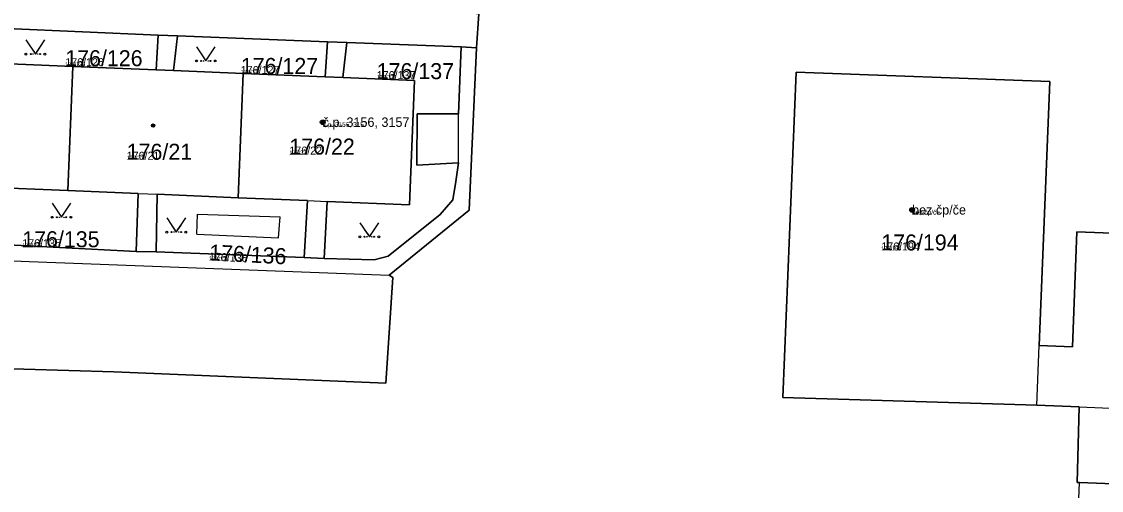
# Model space of a CAD drawing. Extents: x -759873 to -758487, y -975024 to -973516.
# Drawn here: x -759571.4 to -759456.7, y -974909.7 to -974859.9 of the extents above; entities that cross this region are included whole.
import ezdxf

# ---------------------------------------------------------------- set-up
doc = ezdxf.new("R2010")
doc.units = 0
for name, color, linetype in [('KAT_02_hranice parcel', 7, 'Continuous'), ('KAT_03_1000_st čísla parcelní', 7, 'Continuous'), ('KAT_03_1000_čísla parcelní', 7, 'Continuous'), ('KAT_03_1000_čísla popisná', 7, 'Continuous'), ('KAT_03_250_st čísla parcelní', 7, 'Continuous'), ('KAT_03_250_čísla parcelní', 7, 'Continuous'), ('KAT_03_250_čísla popisná', 7, 'Continuous'), ('KAT_03_500_st čísla parcelní', 7, 'Continuous'), ('KAT_03_500_čísla parcelní', 7, 'Continuous'), ('KAT_03_500_čísla popisná', 7, 'Continuous'), ('KAT_04_vnitřní kresba', 7, 'Continuous'), ('KAT_05_1000_značky kultur', 7, 'Continuous'), ('KAT_05_250_značky kultur', 7, 'Continuous'), ('KAT_05_500_značky kultur', 7, 'Continuous'), ('KAT_07_1000_značky budov', 7, 'Continuous'), ('KAT_07_250_značky budov', 7, 'Continuous'), ('KAT_07_500_značky budov', 7, 'Continuous'), ('KAT_14_plocha_budovy', 7, 'Continuous'), ('KAT_14_plocha_pozemek', 7, 'Continuous')]:
    doc.layers.add(name, color=color, linetype=linetype)

msp = doc.modelspace()

# ---------------------------------------------------------------- linework, layer by layer
at = {"layer": 'KAT_02_hranice parcel'}
for p, q in [((-759522.81, -974859.11), (-759523.06, -974862.69)), ((-759572.94, -974860.67), (-759556.86, -974861.35)), ((-759554.8, -974861.42), (-759556.86, -974861.35)), ((-759554.8, -974861.42), (-759538.88, -974862.06)), ((-759536.82, -974862.14), (-759538.88, -974862.06)), ((-759536.82, -974862.14), (-759524.69, -974862.61)), ((-759524.69, -974862.61), (-759523.06, -974862.69)), ((-759566.48, -974877.87), (-759565.93, -974864.69)), ((-759548.38, -974878.62), (-759547.84, -974865.44)), ((-759575.54, -974883.47), (-759559.19, -974884.32)), ((-759559.19, -974884.32), (-759557.09, -974884.36)), ((-759557.09, -974884.36), (-759541.34, -974884.98)), ((-759541.34, -974884.98), (-759539.22, -974885.08))]:
    msp.add_line(p, q, dxfattribs=at)
for points in [[(-759565.93, -974864.69), (-759573.44, -974864.36), (-759572.94, -974860.67)], [(-759556.86, -974861.35), (-759557.08, -974865.04), (-759565.93, -974864.69)], [(-759547.84, -974865.44), (-759555.24, -974865.12), (-759554.8, -974861.42)], [(-759523.06, -974862.69), (-759523.84, -974879.95), (-759532.34, -974886.85), (-759531.93, -974887.1), (-759532.68, -974898.32), (-759561.57, -974897.09), (-759590.3, -974896.25), (-759598.34, -974895.81)], [(-759538.88, -974862.06), (-759539.12, -974865.79), (-759547.84, -974865.44)], [(-759539.22, -974885.08), (-759538.93, -974879.01), (-759530.18, -974879.37), (-759529.64, -974866.18), (-759537.26, -974865.86), (-759536.82, -974862.14)], [(-759539.22, -974885.08), (-759533.93, -974885.2), (-759532.43, -974884.81), (-759526.92, -974880.39), (-759525.57, -974878.84), (-759525.26, -974876.9), (-759524.97, -974874.9), (-759529.38, -974875.18), (-759529.35, -974869.7), (-759524.95, -974869.72), (-759524.69, -974862.61)], [(-759462.14, -974866.29), (-759463.26, -974894.3), (-759459.73, -974894.44), (-759459.28, -974882.23), (-759445.33, -974882.76), (-759445.56, -974888.94), (-759433.43, -974889.26), (-759433.67, -974896.02), (-759433.88, -974901.49), (-759433.89, -974901.85), (-759452.92, -974901.09), (-759453.26, -974909.07), (-759453.61, -974909.06), (-759458.99, -974908.85), (-759459.25, -974908.84), (-759459.03, -974900.84), (-759463.51, -974900.66), (-759490.49, -974899.84), (-759489.09, -974865.28), (-759462.14, -974866.29)], [(-759575.54, -974883.47), (-759575.23, -974877.51), (-759566.48, -974877.87)], [(-759566.48, -974877.87), (-759558.99, -974878.18), (-759559.19, -974884.32)], [(-759557.09, -974884.36), (-759556.96, -974878.26), (-759548.38, -974878.62)], [(-759548.38, -974878.62), (-759541, -974878.92), (-759541.34, -974884.98)]]:
    msp.add_lwpolyline(points, dxfattribs=at)
at = {"layer": 'KAT_03_1000_čísla popisná'}
for centre in [(-759539.39, -974870.6), (-759476.77, -974879.91)]:
    msp.add_circle(centre, 0.25, dxfattribs=at)
at = {"layer": 'KAT_03_250_čísla popisná'}
for centre in [(-759539.39, -974870.6), (-759476.77, -974879.91)]:
    msp.add_circle(centre, 0.0625, dxfattribs=at)
at = {"layer": 'KAT_03_500_čísla popisná'}
for centre in [(-759539.39, -974870.6), (-759476.77, -974879.91)]:
    msp.add_circle(centre, 0.125, dxfattribs=at)
at = {"layer": 'KAT_04_vnitřní kresba'}
for p, q in [((-759557.08, -974865.04), (-759555.24, -974865.12)), ((-759539.12, -974865.79), (-759537.26, -974865.86)), ((-759524.97, -974874.9), (-759524.95, -974869.72)), ((-759558.99, -974878.18), (-759556.96, -974878.26)), ((-759541, -974878.92), (-759538.93, -974879.01)), ((-759552.76, -974882.49), (-759552.69, -974880.35)), ((-759552.69, -974880.35), (-759543.92, -974880.66)), ((-759544.1, -974882.88), (-759543.92, -974880.66)), ((-759552.76, -974882.49), (-759544.1, -974882.88)), ((-759588.86, -974884.55), (-759570.57, -974885.39)), ((-759570.57, -974885.39), (-759564.91, -974885.6)), ((-759564.91, -974885.6), (-759532.34, -974886.85)), ((-759463.51, -974900.66), (-759463.26, -974894.3)), ((-759459.03, -974900.84), (-759452.92, -974901.09)), ((-759460.02, -974931.99), (-759458.99, -974908.85))]:
    msp.add_line(p, q, dxfattribs=at)
at = {"layer": 'KAT_05_1000_značky kultur'}
for points in [[(-759570.91, -974861.87), (-759569.91, -974863.37), (-759568.91, -974861.87)], [(-759552.8, -974862.6), (-759551.8, -974864.1), (-759550.8, -974862.6)], [(-759568.13, -974879.2), (-759567.13, -974880.7), (-759566.13, -974879.2)], [(-759555.94, -974880.77), (-759554.94, -974882.27), (-759553.94, -974880.77)], [(-759535.43, -974881.27), (-759534.43, -974882.77), (-759533.43, -974881.27)]]:
    msp.add_lwpolyline(points, dxfattribs=at)
for centre in [(-759570.91, -974863.37), (-759568.91, -974863.37), (-759552.8, -974864.1), (-759550.8, -974864.1), (-759568.13, -974880.7), (-759566.13, -974880.7), (-759555.94, -974882.27), (-759553.94, -974882.27), (-759535.43, -974882.77), (-759533.43, -974882.77)]:
    msp.add_circle(centre, 0.1, dxfattribs=at)
at = {"layer": 'KAT_05_250_značky kultur'}
for points in [[(-759570.16, -974862.99), (-759569.91, -974863.37), (-759569.66, -974862.99)], [(-759552.05, -974863.72), (-759551.8, -974864.1), (-759551.55, -974863.72)], [(-759567.38, -974880.32), (-759567.13, -974880.7), (-759566.88, -974880.32)], [(-759555.19, -974881.89), (-759554.94, -974882.27), (-759554.69, -974881.89)], [(-759534.68, -974882.39), (-759534.43, -974882.77), (-759534.18, -974882.39)]]:
    msp.add_lwpolyline(points, dxfattribs=at)
for centre in [(-759570.16, -974863.37), (-759569.66, -974863.37), (-759552.05, -974864.1), (-759551.55, -974864.1), (-759567.38, -974880.7), (-759566.88, -974880.7), (-759555.19, -974882.27), (-759554.69, -974882.27), (-759534.68, -974882.77), (-759534.18, -974882.77)]:
    msp.add_circle(centre, 0.025, dxfattribs=at)
at = {"layer": 'KAT_05_500_značky kultur'}
for points in [[(-759570.41, -974862.62), (-759569.91, -974863.37), (-759569.41, -974862.62)], [(-759552.3, -974863.35), (-759551.8, -974864.1), (-759551.3, -974863.35)], [(-759567.63, -974879.95), (-759567.13, -974880.7), (-759566.63, -974879.95)], [(-759555.44, -974881.52), (-759554.94, -974882.27), (-759554.44, -974881.52)], [(-759534.93, -974882.02), (-759534.43, -974882.77), (-759533.93, -974882.02)]]:
    msp.add_lwpolyline(points, dxfattribs=at)
for centre in [(-759570.41, -974863.37), (-759569.41, -974863.37), (-759552.3, -974864.1), (-759551.3, -974864.1), (-759567.63, -974880.7), (-759566.63, -974880.7), (-759555.44, -974882.27), (-759554.44, -974882.27), (-759534.93, -974882.77), (-759533.93, -974882.77)]:
    msp.add_circle(centre, 0.05, dxfattribs=at)
at = {"layer": 'KAT_07_1000_značky budov'}
for centre in [(-759557.41, -974870.96), (-759539.4, -974870.6), (-759476.78, -974879.91)]:
    msp.add_circle(centre, 0.175, dxfattribs=at)
at = {"layer": 'KAT_07_250_značky budov'}
for centre in [(-759557.4, -974870.96), (-759539.39, -974870.6), (-759476.77, -974879.91)]:
    msp.add_circle(centre, 0.0437, dxfattribs=at)
at = {"layer": 'KAT_07_500_značky budov'}
for centre in [(-759557.4, -974870.96), (-759539.39, -974870.6), (-759476.77, -974879.91)]:
    msp.add_circle(centre, 0.0875, dxfattribs=at)
at = {"layer": 'KAT_14_plocha_budovy'}
for points in [[(-759566.48, -974877.87), (-759565.93, -974864.69), (-759573.44, -974864.36), (-759575.29, -974864.28), (-759584.03, -974863.94), (-759591.44, -974863.61), (-759593.3, -974863.54), (-759602.01, -974863.19), (-759609.38, -974862.87), (-759611.29, -974862.79), (-759620.1, -974862.45), (-759620.64, -974875.63), (-759613.14, -974875.94), (-759611.1, -974876.02), (-759602.55, -974876.37), (-759595.19, -974876.68), (-759593.14, -974876.76), (-759584.58, -974877.12), (-759577.2, -974877.42), (-759575.23, -974877.51)], [(-759556.96, -974878.26), (-759548.38, -974878.62), (-759541, -974878.92), (-759538.93, -974879.01), (-759530.18, -974879.37), (-759529.64, -974866.18), (-759537.26, -974865.86), (-759539.12, -974865.79), (-759547.84, -974865.44), (-759555.24, -974865.12), (-759557.08, -974865.04), (-759565.93, -974864.69), (-759566.48, -974877.87), (-759558.99, -974878.18)], [(-759463.26, -974894.3), (-759462.14, -974866.29), (-759489.09, -974865.28), (-759490.49, -974899.84), (-759463.51, -974900.66)]]:
    msp.add_lwpolyline(points, close=True, dxfattribs=at)
at = {"layer": 'KAT_14_plocha_pozemek'}
for points in [[(-759445.5, -974855.85), (-759459.93, -974855.14), (-759460.02, -974857.37), (-759508.63, -974855.12), (-759522.81, -974859.11), (-759523.06, -974862.69), (-759523.84, -974879.95), (-759532.34, -974886.85), (-759531.93, -974887.1), (-759532.68, -974898.32), (-759561.57, -974897.09), (-759590.3, -974896.25), (-759598.34, -974895.81), (-759598.59, -974907.75), (-759628.97, -974906.63), (-759630.26, -974935.59)], [(-759572.94, -974860.67), (-759556.86, -974861.35), (-759554.8, -974861.42), (-759538.88, -974862.06), (-759536.82, -974862.14), (-759524.69, -974862.61), (-759523.06, -974862.69), (-759522.81, -974859.11), (-759523.09, -974859.11), (-759524.63, -974859.04), (-759536.81, -974858.55), (-759538.86, -974858.47), (-759555.7, -974857.75), (-759557.3, -974857.72), (-759558.86, -974857.64), (-759572.99, -974857.06)], [(-759590.3, -974896.25), (-759561.57, -974897.09), (-759532.68, -974898.32), (-759531.93, -974887.1), (-759532.34, -974886.85), (-759523.84, -974879.95), (-759523.06, -974862.69), (-759524.69, -974862.61), (-759524.95, -974869.72), (-759529.35, -974869.7), (-759529.38, -974875.18), (-759524.97, -974874.9), (-759525.26, -974876.9), (-759525.57, -974878.84), (-759526.92, -974880.39), (-759532.43, -974884.81), (-759533.93, -974885.2), (-759539.22, -974885.08), (-759541.34, -974884.98), (-759557.09, -974884.36), (-759559.19, -974884.32), (-759575.54, -974883.47)]]:
    msp.add_lwpolyline(points, dxfattribs=at)
for points in [[(-759566.48, -974877.87), (-759565.93, -974864.69), (-759573.44, -974864.36), (-759572.94, -974860.67), (-759575.05, -974860.6), (-759575.29, -974864.28), (-759584.03, -974863.94), (-759584.58, -974877.12), (-759577.2, -974877.42), (-759577.59, -974883.34), (-759575.54, -974883.47), (-759575.23, -974877.51)], [(-759572.94, -974860.67), (-759573.44, -974864.36), (-759565.93, -974864.69), (-759557.08, -974865.04), (-759556.86, -974861.35)], [(-759557.09, -974884.36), (-759556.96, -974878.26), (-759548.38, -974878.62), (-759547.84, -974865.44), (-759555.24, -974865.12), (-759554.8, -974861.42), (-759556.86, -974861.35), (-759557.08, -974865.04), (-759565.93, -974864.69), (-759566.48, -974877.87), (-759558.99, -974878.18), (-759559.19, -974884.32)], [(-759554.8, -974861.42), (-759555.24, -974865.12), (-759547.84, -974865.44), (-759539.12, -974865.79), (-759538.88, -974862.06)], [(-759529.64, -974866.18), (-759537.26, -974865.86), (-759536.82, -974862.14), (-759538.88, -974862.06), (-759539.12, -974865.79), (-759547.84, -974865.44), (-759548.38, -974878.62), (-759541, -974878.92), (-759541.34, -974884.98), (-759539.22, -974885.08), (-759538.93, -974879.01), (-759530.18, -974879.37)], [(-759524.97, -974874.9), (-759529.38, -974875.18), (-759529.35, -974869.7), (-759524.95, -974869.72), (-759524.69, -974862.61), (-759536.82, -974862.14), (-759537.26, -974865.86), (-759529.64, -974866.18), (-759530.18, -974879.37), (-759538.93, -974879.01), (-759539.22, -974885.08), (-759533.93, -974885.2), (-759532.43, -974884.81), (-759526.92, -974880.39), (-759525.57, -974878.84), (-759525.26, -974876.9)], [(-759462.14, -974866.29), (-759463.26, -974894.3), (-759459.73, -974894.44), (-759459.28, -974882.23), (-759445.33, -974882.76), (-759445.56, -974888.94), (-759433.43, -974889.26), (-759433.67, -974896.02), (-759433.88, -974901.49), (-759433.89, -974901.85), (-759452.92, -974901.09), (-759453.26, -974909.07), (-759453.61, -974909.06), (-759458.99, -974908.85), (-759459.25, -974908.84), (-759459.03, -974900.84), (-759463.51, -974900.66), (-759490.49, -974899.84), (-759489.09, -974865.28)], [(-759462.14, -974866.29), (-759489.09, -974865.28), (-759490.49, -974899.84), (-759463.51, -974900.66), (-759459.03, -974900.84), (-759459.25, -974908.84), (-759458.99, -974908.85), (-759453.61, -974909.06), (-759453.26, -974909.07), (-759452.92, -974901.09), (-759433.89, -974901.85), (-759433.88, -974901.49), (-759433.67, -974896.02), (-759433.43, -974889.26), (-759445.56, -974888.94), (-759445.33, -974882.76), (-759459.28, -974882.23), (-759459.73, -974894.44), (-759463.26, -974894.3)], [(-759559.19, -974884.32), (-759558.99, -974878.18), (-759566.48, -974877.87), (-759575.23, -974877.51), (-759575.54, -974883.47)], [(-759541.34, -974884.98), (-759541, -974878.92), (-759548.38, -974878.62), (-759556.96, -974878.26), (-759557.09, -974884.36)]]:
    msp.add_lwpolyline(points, close=True, dxfattribs=at)

# ---------------------------------------------------------------- texts
at = {"layer": 'KAT_03_1000_st čísla parcelní'}
for s, p in [('176/21', (-759560.21, -974874.59)), ('176/22', (-759542.93, -974874.04)), ('176/194', (-759480.05, -974884.22))]:
    msp.add_text(s, height=1.7, dxfattribs=at).set_placement(p)
at = {"layer": 'KAT_03_1000_čísla parcelní'}
for s, p in [('176/126', (-759566.74, -974864.66)), ('176/127', (-759548.09, -974865.48)), ('176/137', (-759533.65, -974866.03)), ('176/135', (-759571.31, -974883.88))]:
    msp.add_text(s, height=1.7, dxfattribs=at).set_placement(p)
msp.add_text('176/136', height=1.7, rotation=357, dxfattribs=at).set_placement((-759551.49, -974885.27))
at = {"layer": 'KAT_03_1000_čísla popisná'}
for s, p in [('č.p. 3156, 3157', (-759539.39, -974871.1)), ('bez čp/če', (-759476.77, -974880.41))]:
    msp.add_text(s, height=1, dxfattribs=at).set_placement(p)
at = {"layer": 'KAT_03_250_st čísla parcelní'}
for s, p in [('176/21', (-759560.21, -974874.59)), ('176/22', (-759542.93, -974874.04)), ('176/194', (-759480.05, -974884.22))]:
    msp.add_text(s, height=0.425, dxfattribs=at).set_placement(p)
at = {"layer": 'KAT_03_250_čísla parcelní'}
for s, p in [('176/126', (-759566.74, -974864.66)), ('176/127', (-759548.09, -974865.48)), ('176/137', (-759533.65, -974866.03)), ('176/135', (-759571.31, -974883.88))]:
    msp.add_text(s, height=0.425, dxfattribs=at).set_placement(p)
msp.add_text('176/136', height=0.425, rotation=357, dxfattribs=at).set_placement((-759551.49, -974885.27))
at = {"layer": 'KAT_03_250_čísla popisná'}
for s, p in [('č.p. 3156, 3157', (-759539.39, -974871.1)), ('bez čp/če', (-759476.77, -974880.41))]:
    msp.add_text(s, height=0.25, dxfattribs=at).set_placement(p)
at = {"layer": 'KAT_03_500_st čísla parcelní'}
for s, p in [('176/22', (-759542.93, -974874.04)), ('176/21', (-759560.21, -974874.59)), ('176/194', (-759480.05, -974884.22))]:
    msp.add_text(s, height=0.85, dxfattribs=at).set_placement(p)
at = {"layer": 'KAT_03_500_čísla parcelní'}
for s, p in [('176/126', (-759566.74, -974864.66)), ('176/127', (-759548.09, -974865.48)), ('176/137', (-759533.65, -974866.03)), ('176/135', (-759571.31, -974883.88))]:
    msp.add_text(s, height=0.85, dxfattribs=at).set_placement(p)
msp.add_text('176/136', height=0.85, rotation=357, dxfattribs=at).set_placement((-759551.49, -974885.27))
at = {"layer": 'KAT_03_500_čísla popisná'}
for s, p in [('č.p. 3156, 3157', (-759539.39, -974871.1)), ('bez čp/če', (-759476.77, -974880.41))]:
    msp.add_text(s, height=0.5, dxfattribs=at).set_placement(p)

doc.saveas('drawing.dxf')
